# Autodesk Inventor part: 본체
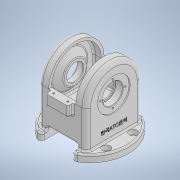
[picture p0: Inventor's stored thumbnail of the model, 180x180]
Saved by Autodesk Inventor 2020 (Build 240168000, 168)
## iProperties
Created: 2024-08
Part Number: 본체
Material: 일반
Document SubType Name: Modeling
Designer: oem
Density: 1 g/cm^3
Appearance: 기본값
Mass: 444.002 g
Surface Area: 1052.82 cm^2
Volume: 444.002 cm^3
Author: oem
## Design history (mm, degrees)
sketch "스케치2"
  geometry: L1 (0, 51)-(-81, 51); L2 (-81, 51)-(-81, -51); L3 (-81, -51)-(0, -51); L4 (51, 0)-(51, 0); A1 r 51 centre (0, 0) between (51, 0) and (0, 51); A2 r 51 centre (0, 0) between (0, -51) and (51, 0); 3 further points
  constraints: 8 end point, 4 point on circle, 4 tangent, 2 centre point, 2 parallel, 2 point on line, 1 concentric, 1 horizontal, 1 perpendicular
  dimensions: "d3" = 132 distance of L2.end point (51, -51); "d4" = 102 distance of L1.end L2.end; "d5" = 51 radius of A1; "d6" = 51 distance from line of point (0, 0) L1; "d7" = 81 distance from line of point (0, 0) L2
extrude "돌출2" new body sketch "스케치2" distance "d8" = 88; taper "d9" = 0 deg
sketch "스케치3"
  geometry: L1 (-69, 132)-(-19, 132); L2 (-19, 132)-(-19, 81); L3 (-19, 81)-(-69, 81); L4 (-69, 81)-(-69, 132); L5 (0, 81)-(0, 81) reference; L6 (0, 81)-(-88, 81) reference; L7 (-88, 81)-(-88, 81) reference; L8 (0, 81)-(-88, 81) reference; L9 (0, 132)-(-88, 132) reference; L10 (-88, 0)-(-88, 81) reference; 1 further point
  constraints: 8 end point, 2 parallel, 1 horizontal, 1 perpendicular
  dimensions: "d10" = 50 distance of L1.start L1.end; "d11" = 0 distance between parallel lines of L9 L1; "d12" = 19 distance between parallel lines of L4 L10; "d13" = 51 distance of L1.end L2.end
extrude "돌출3" cut sketch "스케치3" extent not by distance; stored distance "d14" = 0; taper "d15" = 0 deg
sketch "스케치6"
  geometry: L1 (0, 102)-(0, 0) reference; L2 (0, 0)-(-88, 0) reference; C1 r 71 at (-44, 51); 2 further points
  constraints: 1 centre point, 1 coincident
  dimensions: "d17" = 44 distance from line of point (-44, 51) L1; "d18" = 51 distance from line of point (-44, 51) L2; "d19" = 142 diameter of C1
extrude "돌출4" join sketch "스케치6" distance "d20" = 13; taper "d21" = 0 deg
node "작업 평면1"
sketch "스케치7"
  geometry: L1 (53, -81)-(-3, -81); L2 (-3, -81)-(-3, -62); L3 (-3, -62)-(53, -62); L4 (53, -62)-(53, -81); L5 (-46, -81)-(96, -81) reference; 1 further point
  constraints: 8 end point, 2 parallel, 1 horizontal, 1 horizontal alignment, 1 perpendicular
  dimensions: "d23" = 56 distance of L1.start L1.end; "d24" = 19 distance of L3.end L1.start; "d25" = 43 distance from line of L4 L5.end
extrude "돌출5" cut sketch "스케치7" extent not by distance; stored distance "d26" = 0; taper "d27" = 0 deg
sketch "스케치9"
  geometry: A1 r 51 centre (0, 0) between (51, 0) and (-51, 0) reference; 2 further points
  constraints: 1 coincident
sketch "스케치10"
  geometry: A1 r 51 centre (0, 0) between (51, 0) and (-51, 0) reference; 2 further points
  constraints: 1 coincident
sketch "스케치11"
  geometry: L1 (5, 0)-(45, 0); L2 (45, 0)-(45, -20); L3 (45, -20)-(5, -20); L4 (5, -20)-(5, 0); L5 (-19, -68)-(-19, 0) reference; 1 further point
  constraints: 8 end point, 2 parallel, 1 horizontal, 1 horizontal alignment, 1 perpendicular
  dimensions: "d42" = 40 distance of L2.end L3.end; "d43" = 20 distance of L1.end L2.end; "d44" = 24 distance between parallel lines of L4 L5
extrude "돌출6" join sketch "스케치11" distance "d45" = 10; taper "d46" = 0 deg
sketch "스케치12"
  geometry: L1 (12, -3)-(38, -3); L2 (38, -3)-(38, 105); L3 (38, 105)-(12, 105); L4 (12, 105)-(12, -3); L5 (5, 102)-(5, 112) reference; 1 further point
  constraints: 8 end point, 2 parallel, 1 horizontal, 1 perpendicular
  dimensions: "d47" = 26 distance of L2.end L3.end; "d48" = 108 distance of L1.end L2.end; "d49" = 54 distance from line of L3 point (69, 51); "d50" = 7 distance from line of L3.end L5
hole "구멍3" sketch "스케치12" at (38, -3), (12, -3), (12, 105), (38, 105) diameter "d51" = 3.242; stored, may be unused: countersink angle "d55" = 90 deg, drill point angle "d57" = 118 deg; dims "d52" = 8, "d53" = 60, "d54" = 2, "d56" = 10
sketch "스케치13"
  geometry: L1 (51, 0)-(51, -68) reference; L2 (-51, -68)-(-51, 0) reference; L3 (-46, -41)-(-46, 0); L4 (46, 0)-(46, -41); L5 (-46, -41)-(46, -41); L6 (65.246, -81)-(-65.246, -81) reference; A1 r 51 centre (0, 0) between (51, 0) and (-51, 0) reference; A2 r 46 centre (0, 0) between (46, 0) and (-46, 0); 1 further point
  constraints: 6 end point, 2 point on circle, 1 centre point, 1 horizontal
  dimensions: "d58" = 5 radial gap between concentric circles of A1 A2; "d59" = 40 distance between parallel lines of L5 L6
extrude "돌출7" cut sketch "스케치13" distance "d60" = 14; taper "d61" = 0 deg
sketch "스케치14"
  geometry: L1 (51, 0)-(51, -68) reference; L2 (-51, -68)-(-51, 0) reference; L3 (-46, -41)-(-46, 0); L4 (46, 0)-(46, -41); L5 (-46, -41)-(46, -41); L6 (65.246, -81)-(-65.246, -81) reference; A1 r 46 centre (0, 0) between (46, 0) and (-46, 0) reference; A2 r 51 centre (0, 0) between (51, 0) and (-51, 0) reference; A3 r 46 centre (0, 0) between (46, 0) and (-46, 0); 1 further point
  constraints: 6 end point, 2 point on circle, 1 centre point, 1 horizontal
  dimensions: "d62" = 5 radial gap between concentric circles of A2 A3; "d63" = 40 distance between parallel lines of L5 L6
extrude "돌출8" cut sketch "스케치14" distance "d64" = 14; taper "d65" = 0 deg
sketch "스케치15"
  geometry: L1 (46, -41)-(46, 0) reference; L2 (-46, 0)-(-46, -41) reference; L3 (-46, -41)-(46, -41) reference; L4 (-46, -41)-(46, -41); L5 (46, -41)-(46, 0); L6 (46, 0)-(-46, 0); L7 (-46, 0)-(-46, -41); 1 further point
  constraints: 8 end point, 2 parallel, 1 horizontal, 1 perpendicular
extrude "돌출9" cut sketch "스케치15" stored distance "d66" = 14; taper "d67" = 0 deg
sketch "스케치16"
  geometry: C1 r 33.5 at (0, 0); 1 further point
  constraints: 1 centre point, 1 coincident
  dimensions: "d68" = 67 diameter of C1
extrude "돌출10" join sketch "스케치16" distance "d69" = 12; taper "d70" = -45 deg
node "작업 평면2"
sketch "스케치17"
  geometry: A1 r 51 centre (0, 0) between (51, 0) and (-51, 0) reference; 2 further points
  constraints: 1 coincident
hole "구멍4" sketch "스케치17" at (0, 0) diameter "d72" = 37; stored, may be unused: countersink angle "d76" = 90 deg, drill point angle "d78" = 0 deg; dims "d73" = 8, "d74" = 60, "d75" = 2, "d77" = 15
sketch "스케치18"
  geometry: A1 r 51 centre (0, 0) between (51, 0) and (-51, 0) reference; 2 further points
  constraints: 1 coincident
hole "구멍5" sketch "스케치18" at (0, 0) diameter "d79" = 37; stored, may be unused: countersink angle "d83" = 90 deg, drill point angle "d85" = 0 deg; dims "d80" = 8, "d81" = 60, "d82" = 2, "d84" = 15
sketch "스케치19"
  geometry: C1 r 18.5 at (0, 0) reference; 2 further points
  constraints: 1 coincident
hole "구멍6" sketch "스케치19" at (0, 0) diameter "d86" = 32; stored, may be unused: countersink angle "d90" = 90 deg, drill point angle "d92" = 0 deg; dims "d87" = 8, "d88" = 60, "d89" = 2, "d91" = 15
sketch "스케치20"
  geometry: L1 (-65.246, -81)-(65.246, -81) reference; 2 further points
  constraints: 1 vertical alignment, 1 other
  dimensions: "d93" = 30 distance from line of point (0, -51) L1
feature "엠보싱1" sketch "스케치20" dims "d94" = 0.5, "d95" = 0
sketch "스케치21"
  geometry: L1 (-99, -26)-(11, -26); L2 (11, -26)-(11, -76); L3 (11, -76)-(-99, -76); L4 (-99, -76)-(-99, -26); A1 r 71 centre (-44, -51) between (-16, -116.246) and (-16, 14.246) reference; 1 further point
  constraints: 8 end point, 2 parallel, 1 horizontal, 1 perpendicular
  dimensions: "d96" = 50 distance of L1.end L2.end; "d97" = 110 distance of L1.start L1.end; "d98" = 25 distance from line of A1.centre L1; "d99" = 55 distance from line of A1.centre L2
hole "구멍7" sketch "스케치21" at (11, -76), (11, -26), (-99, -76), (-99, -26) diameter "d100" = 9; stored, may be unused: countersink angle "d104" = 90 deg, drill point angle "d106" = 0 deg; dims "d101" = 8, "d102" = 15, "d103" = 8.8, "d105" = 15
sketch "스케치22"
  geometry: L1 (0, 0)-(23, 0)
  constraints: 2 end point, 1 horizontal
  dimensions: "d107" = 23 distance of L1.start L1.end
hole "구멍8" sketch "스케치22" at (23, 0) diameter "d108" = 3.242; stored, may be unused: countersink angle "d112" = 90 deg, drill point angle "d114" = 118 deg; dims "d109" = 8, "d110" = 15, "d111" = 8.8, "d113" = 10
node "작업 평면3"
sketch "스케치23"
  geometry: L1 (72, -102)-(72, 0) reference; L2 (48, 0)-(8, 0) reference; C1 r 30 at (28, -51); 1 further point
  constraints: 1 centre point
  dimensions: "d119" = 60 diameter of C1; "d120" = 44 distance from line of C1.centre L1; "d121" = 51 distance from line of C1.centre L2
extrude "돌출11" cut sketch "스케치23" extent not by distance; stored distance "d122" = 22; taper "d123" = 0 deg
sketch "스케치24"
  geometry: L1 (0, 0)-(23, 0); A1 r 30 centre (0, 0) between (28, 10.77) and (-28, 10.77) reference; 1 further point
  constraints: 2 end point, 1 horizontal
  dimensions: "d124" = 23 distance of L1.start L1.end
hole "구멍9" sketch "스케치24" at (23, 0) diameter "d125" = 3.242; stored, may be unused: countersink angle "d129" = 90 deg, drill point angle "d131" = 118 deg; dims "d126" = 8, "d127" = 15, "d128" = 8.8, "d130" = 10
sketch "스케치25"
  geometry: C1 r 30 at (0, 0) reference; 2 further points
  constraints: 1 coincident
hole "구멍10" sketch "스케치25" at (0, 0) diameter "d135" = 22; stored, may be unused: countersink angle "d139" = 90 deg, drill point angle "d141" = 0 deg; dims "d136" = 8, "d137" = 28, "d138" = 15, "d140" = 40
fillet "모깎기1" dims "d142" = 8
chamfer "모따기1" distance "d143" = 1; stored, may be unused: second distance "d144" = 2, angle "d145" = 45 deg
fillet "모깎기2" dims "d146" = 0.3
fillet "모깎기3" dims "d147" = 6
fillet "모깎기4" dims "d148" = 3
fillet "모깎기5" dims "d149" = 3
fillet "모깎기6" dims "d150" = 3
fillet "모깎기7" dims "d151" = 3
fillet "모깎기8" dims "d152" = 3
fillet "모깎기9" dims "d153" = 3
node "솔리드2"
mirror "미러1"
mirror "미러2"
pattern_circular "원형 패턴1" dims angle "d116" = 360 deg
mirror "미러3"
pattern_circular "원형 패턴2" dims angle "d133" = 360 deg
node "투영된 루프1"
feature "A9D066F2-1C7D-4E18-AEED-F7BC21143FA4" dims "d72" = 37, "d73" = 8, "d74" = 60, "d75" = 2, "d76" = 90 deg, "d77" = 15, "d78" = 0
other parameters: "d22" = 78, "d71" = -44, "d118" = -3
